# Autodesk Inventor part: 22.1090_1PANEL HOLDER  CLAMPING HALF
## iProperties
Created: 2007-04
Part Number: 22.1090_1PANEL HOLDER  CLAMPING HALF
Material: PVC-U
Document SubType Name: Modeling
Designer: Andy Moles
Mass: 10.4068 g
Surface Area: 58.3002 cm^2
Volume: 7.43341 cm^3
Density: 1.4 g/cm^3
Author: Andy Moles
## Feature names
1. Extrusion1
